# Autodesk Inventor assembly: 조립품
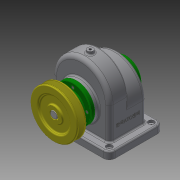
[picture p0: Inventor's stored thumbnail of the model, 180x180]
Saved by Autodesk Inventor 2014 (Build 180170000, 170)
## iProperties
Created: 2017-11
Part Number: 조립품
Document SubType Name: Assembly
Designer: net
Author: net
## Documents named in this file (14)
- C:\Users\net\Desktop\471107V1038\조립품.iam
- C:\Users\net\Desktop\471107V1038\V-벨트풀리.ipt
- C:\Users\net\Desktop\471107V1038\뒤커버.ipt
- C:\Users\net\Desktop\471107V1038\멈춤나사 - M4 x 10.ipt
- 멈춤나사 - M4 x 10.ipt
- C:\Users\net\Desktop\471107V1038\베어링 6002.ipt
- C:\Users\net\Desktop\471107V1038\본체.ipt
- C:\Users\net\Desktop\471107V1038\볼트 M3 x 8.ipt
- C:\Users\net\Desktop\471107V1038\스퍼기어.ipt
- C:\Users\net\Desktop\471107V1038\앞커버.ipt
- C:\Users\net\Desktop\471107V1038\오일 실 15 30 7.ipt
- C:\Users\net\Desktop\471107V1038\축.ipt
- C:\Users\net\Desktop\471107V1038\키 - 5 x 5 x 18.ipt
- C:\Users\net\Desktop\471107V1038\키 - 6 x 6 x 22.ipt
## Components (1 placed, 1 different names)
1. V-벨트풀리:1
